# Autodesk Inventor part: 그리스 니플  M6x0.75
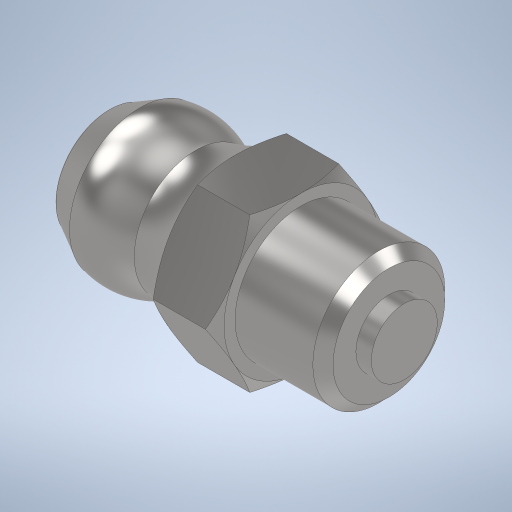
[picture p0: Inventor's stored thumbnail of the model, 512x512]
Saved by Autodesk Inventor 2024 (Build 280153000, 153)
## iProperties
Created: 2024-11
Part Number: 그리스 니플  M6x0.75
Material: 강철, 연강
Description: 윤활 니플, 원추 유형 A
Document SubType Name: Modeling
Designer: user
Density: 7.85 g/cm^3
Appearance: 기본값
Author: jhkim
Sending System: Autodesk Inventor 2025
Preprocessor: ST-DEVELOPER v20
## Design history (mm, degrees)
node "그리스 니플 M6x0.751"
node "솔리드1"
body "Solid1"
